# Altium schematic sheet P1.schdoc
size 297 x 209 mm; Symbol: Sheet-Symbol_A4; Company: 嘉立创EDA; Version: V1.0; Page Size: A4; @Project Name: 缓冲器; @Page Count: 1; @Update Date: 2025-10-20; @Create Date: 2025-10-20; @Schematic Name: Schematic1; @Page No: 1; @Page Name: P1; Device: Sheet-Symbol_A4; Border: 1; Title Block Position: 3; Width: 1170; Height: 825; Region Start: 1; X Region Count: 6; Y Region Count: 4; Blade Width: 10; @Board Name: Board1; @Create Time: 13:55:46; @Update Time: 14:26:49
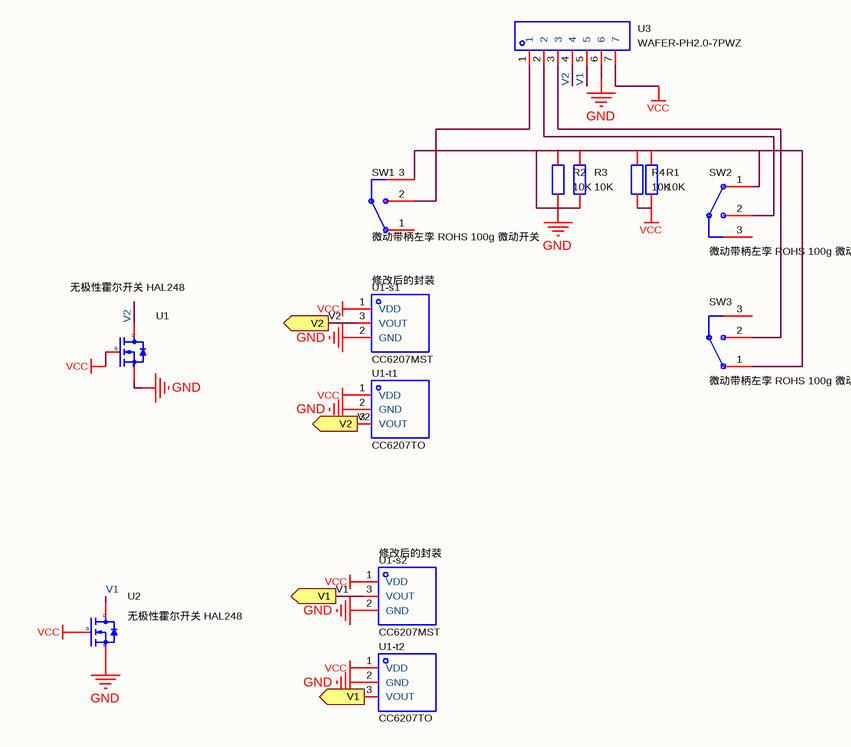
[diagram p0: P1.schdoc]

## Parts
R1  10K  [R0603]
R2  10K  [R0603]
R3  10K  [R0603]
R4  10K  [R0603]
SW1  微动带柄左孪 ROHS 100g 微动开关  [KEY-TH_100GMICROSWITCH]
SW2  微动带柄左孪 ROHS 100g 微动开关  [KEY-TH_100GMICROSWITCH]
SW3  微动带柄左孪 ROHS 100g 微动开关  [KEY-TH_100GMICROSWITCH]
U1  无极性霍尔开关 HAL248  [SOT-23-3_L2.9-W1.6-P1.90-LS2.8-BR]
U1-s1  CC6207MST  [SOT-23-3_L2.9-W1.6-P1.90-LS2.8-BR]
U1-s2  CC6207MST  [SOT-23-3_L2.9-W1.6-P1.90-LS2.8-BR]
U1-t1  CC6207TO  [TO-92S-3_L4.1-W1.7-P1.27-L]
U1-t2  CC6207TO  [TO-92S-3_L4.1-W1.7-P1.27-L]
U2  无极性霍尔开关 HAL248  [SOT-23-3_L2.9-W1.6-P1.90-LS2.8-BR]
U3  WAFER-PH2.0-7PWZ  [CONN-TH_7P-P2.00_XUNPU_WAFER-PH2.0-7PWZ]

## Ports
V1 (out), V2 (out)

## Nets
GND: R1.2 R2.1 R2.2 R3.1 R3.2 R4.2 SW1.3 SW2.1 SW3.1 U1.2(S) U1-s1.2(GND) U1-s2.2(GND) U1-t1.2(GND) U1-t2.2(GND) U2.2(S) U3.6
VCC: R1.1 R4.1 U1.1(G) U1-s1.1(VDD) U1-s2.1(VDD) U1-t1.1(VDD) U1-t2.1(VDD) U2.1(G) U3.7
V1: U1-s2.3(VOUT) U1-t2.3(VOUT) U2.3(D) U3.5 ; port V1
V2: U1.3(D) U1-s1.3(VOUT) U1-t1.3(VOUT) U3.4 ; port V2
NetSW1_2: SW1.2 U3.1
NetSW2_2: SW2.2 U3.2
NetSW3_2: SW3.2 U3.3

Not connected (* = marked no-connect by the designer): SW1 1; SW2 3; SW3 3

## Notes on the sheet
- (near U1-s1) 修改后的封装
- (near U1-s2) 修改后的封装

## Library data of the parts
R1-R4 = Res_0603: Symbol: 电阻; ConvertToPcb: yes; ModelId: fc143cca1e79419f9cd78b61e9279f08; ModelTransform: 31.8897,63.7794,0,90,0,0,0,0,0
SW1 = 微动带柄左孪 ROHS 100g 微动开关: Symbol: Jaw handle left twins ROHS 100g Micro Switch; 3D Model: 2f87a4f5d49c48c2851aec22ca877221; 3D Model Transform: 540.57065,438.976,0,0,0,0,20.079,210.63,-129.921; AddInBom: yes
SW2 SW3 = 微动带柄左孪 ROHS 100g 微动开关: Symbol: Jaw handle left twins ROHS 100g Micro Switch; AddInBom: yes; ModelId: 2f87a4f5d49c48c2851aec22ca877221; ModelTransform: 540.57065,438.976,0,0,0,0,20.079,210.63,-129.921
U1 U2 = 无极性霍尔开关 HAL248: Convert to PCB: no; AddInBom: yes; ModelId: 89cb27a44ab2466697082bb9fd73a7d0; ModelName: SOT-23-3L_L2.9-W1.6-H1.1-LS2.8-P0.95; ModelTransform: 114.173,110.236,0,90,0,0,0,0,0
U1-s1 U1-s2 = CC6207MST: 微功耗   32Hz,±20Gs,全极性霍尔开关; Manufacturer: CrossChip(成都芯进); AddInBom: yes; ModelId: 89cb27a44ab2466697082bb9fd73a7d00819f05c4eef4c71ace90d822a990e87; ModelName: SOT-23-3L_L2.9-W1.6-H1.1-LS2.8-P0.95; ModelTransform: 114.173,110.236,0,90,0,0,0,0,0; Voltage - Supply: 5V; Operation Points: ±2mT; Release Points: ±1.5mT
U1-t1 U1-t2 = CC6207TO_C880903: 微功耗; Manufacturer: CrossChip(成都芯进); AddInBom: yes; ModelId: 7faeba93400344db9ec21ec73c9923490819f05c4eef4c71ace90d822a990e87; ModelName: TO-92S-3_L4.1-W1.7-H6.5-P1.27-L; ModelTransform: 165.354,66.142,0,0,0,0,0,-5.906,-472.441; Voltage - Supply: 5V; Output Current: 500uA; Operation Points: ±2mT; Release Points: ±1.5mT; Operating Current: 3uA; Sample Frequency: 40Hz
U3 = WAFER-PH2.0-7PWZ: 插针结构:1x7P;间距:2mm;安装方式:弯插;参考系列:PH;总PIN数:7P;排数:1;每排PIN数:7;行距:-;额定电流:2A;触头材质:黄铜;触头镀层:锡;工作温度:-25℃~+85℃;; Manufacturer: XUNPU(讯普); AddInBom: yes; ModelId: 3729955ec03044a68517e4ce582ae43c; ModelTransform: 629.92,248.031,0,0,0,0,0.039,-114.173,-133.858; Pins Structure: 1x7P; Pitch: 2mm; Reference Series: PH; Number of PINs Per Row: 7; Current Rating: 2A; Voltage Rating: 250V; Plastic Material: PA66; Flame Retardant Rating: UL94V-0; Z-Height of the Board: 4.7mm; X-Length of Bottom Edge on Board (Spacing Line): 16mm; Y-Width of Bottom Edge on Board: 6.05mm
